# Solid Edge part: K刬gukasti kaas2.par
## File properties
Author: Türk
Template: iso part.par
Last saved by: Türk
Revision: 3
Application: Solid Edge
Accuracy: 0,990
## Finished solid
Body 1: solid body, 9 faces, 32 edges, 25 vertices.
  Faces by surface: spline 5, plane 4
  Edges by curve: line 16, circle 8, curve on surface 5, spline 3
Bounding box of the edges (mm; curved faces can reach further): 200.000 x 345.000 x 100.000, from (-100, -535, 0) to (100, -190, 99.9999).
Planar faces by outward normal: +y 1, -y 1, -z 2
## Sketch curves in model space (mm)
line (100, -190, 0) -> (95, -190, 0)
arc centre (0, -190, 0) radius 95 from (-95, -190, 0) through (2.8152, -190, 94.9583) to (95, -190, 0)
line (-100, -190, 0) -> (-95, -190, 0)
arc centre (0, -190, 0) radius 100 from (-100, -190, 0) through (2.9633, -190, 99.9561) to (100, -190, 0)
line (100, 0, 0) -> (95, 0, 0)
arc centre (0, 0, 0) radius 95 from (-95, 0, 0) through (2.8152, 0, 94.9583) to (95, 0, 0)
line (-100, 0, 0) -> (-95, 0, 0)
arc centre (0, 0, 0) radius 100 from (-100, 0, 0) through (2.9633, 0, 99.9561) to (100, 0, 0)
arc centre (0, 0, 0) radius 95 from (-95, 0, 0) through (2.8152, 0, 94.9583) to (95, 0, 0)
line (100, 0, 0) -> (95, 0, 0)
arc centre (0, 0, 0) radius 100 from (-100, 0, 0) through (2.9633, 0, 99.9561) to (100, 0, 0)
line (-100, 0, 0) -> (-95, 0, 0)
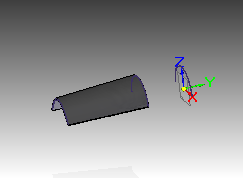
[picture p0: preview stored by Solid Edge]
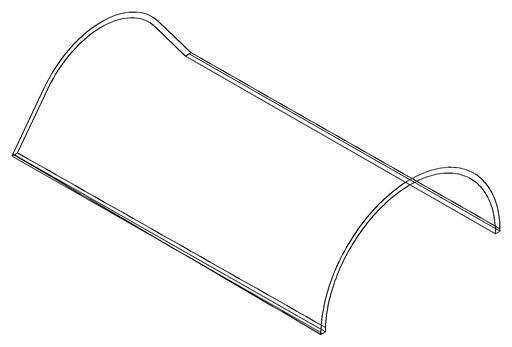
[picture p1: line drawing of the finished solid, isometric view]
